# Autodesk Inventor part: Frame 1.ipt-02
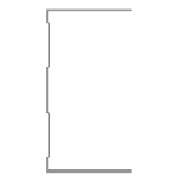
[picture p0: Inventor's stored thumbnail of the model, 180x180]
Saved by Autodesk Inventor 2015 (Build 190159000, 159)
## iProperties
IsCustomPart: 1
Created: 2015-04
Part Number: Frame 1.ipt-02
Material: Aluminum 6061
Description: Kévin Novo
Document SubType Name: Modeling
Standard: Kevin
Designer: suporte
Standards Organization: Kevin
Language: en-US
Size Designation: (Unnamed 2)
Categories: <MemberInstance><Categories><Category DisplayName="Structural Shapes" InternalName="089c4875-fa83-4c05-b084-43b9cc11f5ed" Mnemonic="GRDR"><CategoryParameter Dis
Density: 2.7 g/cm^3
Appearance: Aluminum - Flat
_CCFamilyMember: 2
_CCFamilyDisplayName: Kévin - Kévin Novo
_FrameMemberDoc: Frame Member File
_Version: 15.0.0
_GetPNFromCC: 1
G_W: 50,000 mm
G_H: 75,000 mm
G_L: 2100,000 mm
+4CB7B063-A71F-464C-8F08-7559726A3259+CUTDETAIL1: Notch
Author: suporte
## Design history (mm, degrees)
node "Start Plane"
node "End Plane"
sketch "Sketch"
  geometry: L1 (24.7, 37.5)-(24.7, 36.9); L2 (24.7, 36.9)-(-24.7, 36.9); L3 (-24.7, -36.9)-(24.7, -36.9); L4 (24.7, -36.9)-(24.7, -37.5); L5 (24.7, -37.5)-(-25.3, -37.5); L6 (-25.3, 37.5)-(24.7, 37.5); L7 (-24.7, 36.9)-(-24.7, 31.9); L8 (-24.7, 31.9)-(-23.3, 30.5); L9 (-23.3, 30.5)-(-23.3, 10.934); L10 (-23.3, 10.934)-(-24.7, 9.534); L11 (-24.7, 9.534)-(-24.7, -9.534); L12 (-24.7, -9.534)-(-23.3, -10.934); L13 (-23.3, -10.934)-(-23.3, -30.5); L14 (-23.3, -30.5)-(-24.7, -31.9); L15 (-24.7, -31.9)-(-24.7, -36.9); L16 (-25.3, -37.5)-(-25.3, -31.651); L17 (-25.3, -31.651)-(-23.9, -30.251); L18 (-23.9, -30.251)-(-23.9, -11.183); L19 (-23.9, -11.183)-(-25.3, -9.783); L20 (-25.3, -9.783)-(-25.3, 9.783); L21 (-25.3, 9.783)-(-23.9, 11.183); L22 (-23.9, 11.183)-(-23.9, 30.251); L23 (-23.9, 30.251)-(-25.3, 31.651); L24 (-25.3, 31.651)-(-25.3, 37.5); L25 (-25.3, 0)-(30.37, 0); 3 further points
  constraints: 50 end point, 10 point on line, 9 parallel, 5 perpendicular, 4 equal length, 3 midpoint, 3 vertical, 2 vertical alignment, 1 collinear, 1 horizontal, 1 horizontal alignment
  dimensions: "d3" = 0.6 distance of L1.start L1.end (= d6); "d5" = 75 distance between parallel lines of L5 L6; "d6" = 0.6 distance between parallel lines of L24 L7 (= d8); "d7" = 0.6 distance between parallel lines of L8 L23 (= d8); "d8" = 0.6 distance between parallel lines of L22 L9 (= d12); "Espessura" = 0.6 distance between parallel lines of L17 L14; "d10" = 0.6 distance between parallel lines of L13 L18 (= Espessura); "d11" = 0.6 distance between parallel lines of L12 L19 (= Espessura); "d12" = 0.6 distance between parallel lines of L21 L10 (= d11); "d13" = 5 distance of L2.end L7.end; "d15" = 135 deg angle of L9 L8; "d16" = 2 distance between parallel lines of L24 L9; "d17" = 50 distance of L6.start L1.start
extrude "Body" join sketch "Sketch" stored distance "d24" = 0.13; taper "d25" = 0 deg
node "Driven Length"
  sketch "Sketch10"
    geometry: L1 (0, 0)-(10, 0) reference
    constraints: 2 end point, 1 horizontal
  workplane "Work Plane7"
  sketch "Sketch11"
    geometry: L1 (-2, 0)-(12, 0) reference; L2 (-2, 2100)-(12, 2100) reference
    dimensions: "d27" = 2100 distance between parallel lines of L1 L2 (derived)
workplane "Work Plane8"
workplane "Work Plane9"
workplane "Work Plane10"
sketch "Sketch12"
  geometry: L1 (24.7, 37.5)-(24.7, 36.9); L2 (24.7, 36.9)-(-24.7, 36.9); L3 (-24.7, 36.9)-(-24.7, 31.9); L4 (-24.7, 31.9)-(-23.3, 30.5); L5 (-23.3, 30.5)-(-23.3, 10.934); L6 (-23.3, 10.934)-(-24.7, 9.534); L7 (-24.7, 9.534)-(-24.7, -9.534); L8 (-24.7, -9.534)-(-23.3, -10.934); L9 (-23.3, -10.934)-(-23.3, -30.5); L10 (-23.3, -30.5)-(-24.7, -31.9); L11 (-24.7, -31.9)-(-24.7, -36.9); L12 (-24.7, -36.9)-(24.7, -36.9); L13 (24.7, -36.9)-(24.7, -37.5); L14 (24.7, -37.5)-(-25.3, -37.5); L15 (-25.3, -37.5)-(-25.3, -31.651); L16 (-25.3, -31.651)-(-23.9, -30.251); L17 (-23.9, -30.251)-(-23.9, -11.183); L18 (-23.9, -11.183)-(-25.3, -9.783); L19 (-25.3, -9.783)-(-25.3, 9.783); L20 (-25.3, 9.783)-(-23.9, 11.183); L21 (-23.9, 11.183)-(-23.9, 30.251); L22 (-23.9, 30.251)-(-25.3, 31.651); L23 (-25.3, 31.651)-(-25.3, 37.5); L24 (-25.3, 37.5)-(24.7, 37.5)
  constraints: 48 end point, 10 point on line
extrude "Extrusion3" cut sketch "Sketch12" stored distance "d36" = 0.13; taper "d37" = 0 deg
body "Solid1"
other parameters: "G_OFFSET_START" = 0 [user parameter; used in 1 equation term], "G_OFFSET_END" = 0 [user parameter; used in 1 equation term], "d22" = 0 (computed from G_OFFSET_START), "G_L" = 2100 (= d27) [user parameter], "d34" = 90 deg
